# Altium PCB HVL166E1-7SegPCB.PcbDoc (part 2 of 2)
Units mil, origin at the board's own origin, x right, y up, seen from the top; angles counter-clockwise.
Board outline 2300 x 2421 mil, 2 copper layers (Top Layer, Bottom Layer), stack 62 mil thick; 193 components, 200 nets, 656 pads, 241 vias.
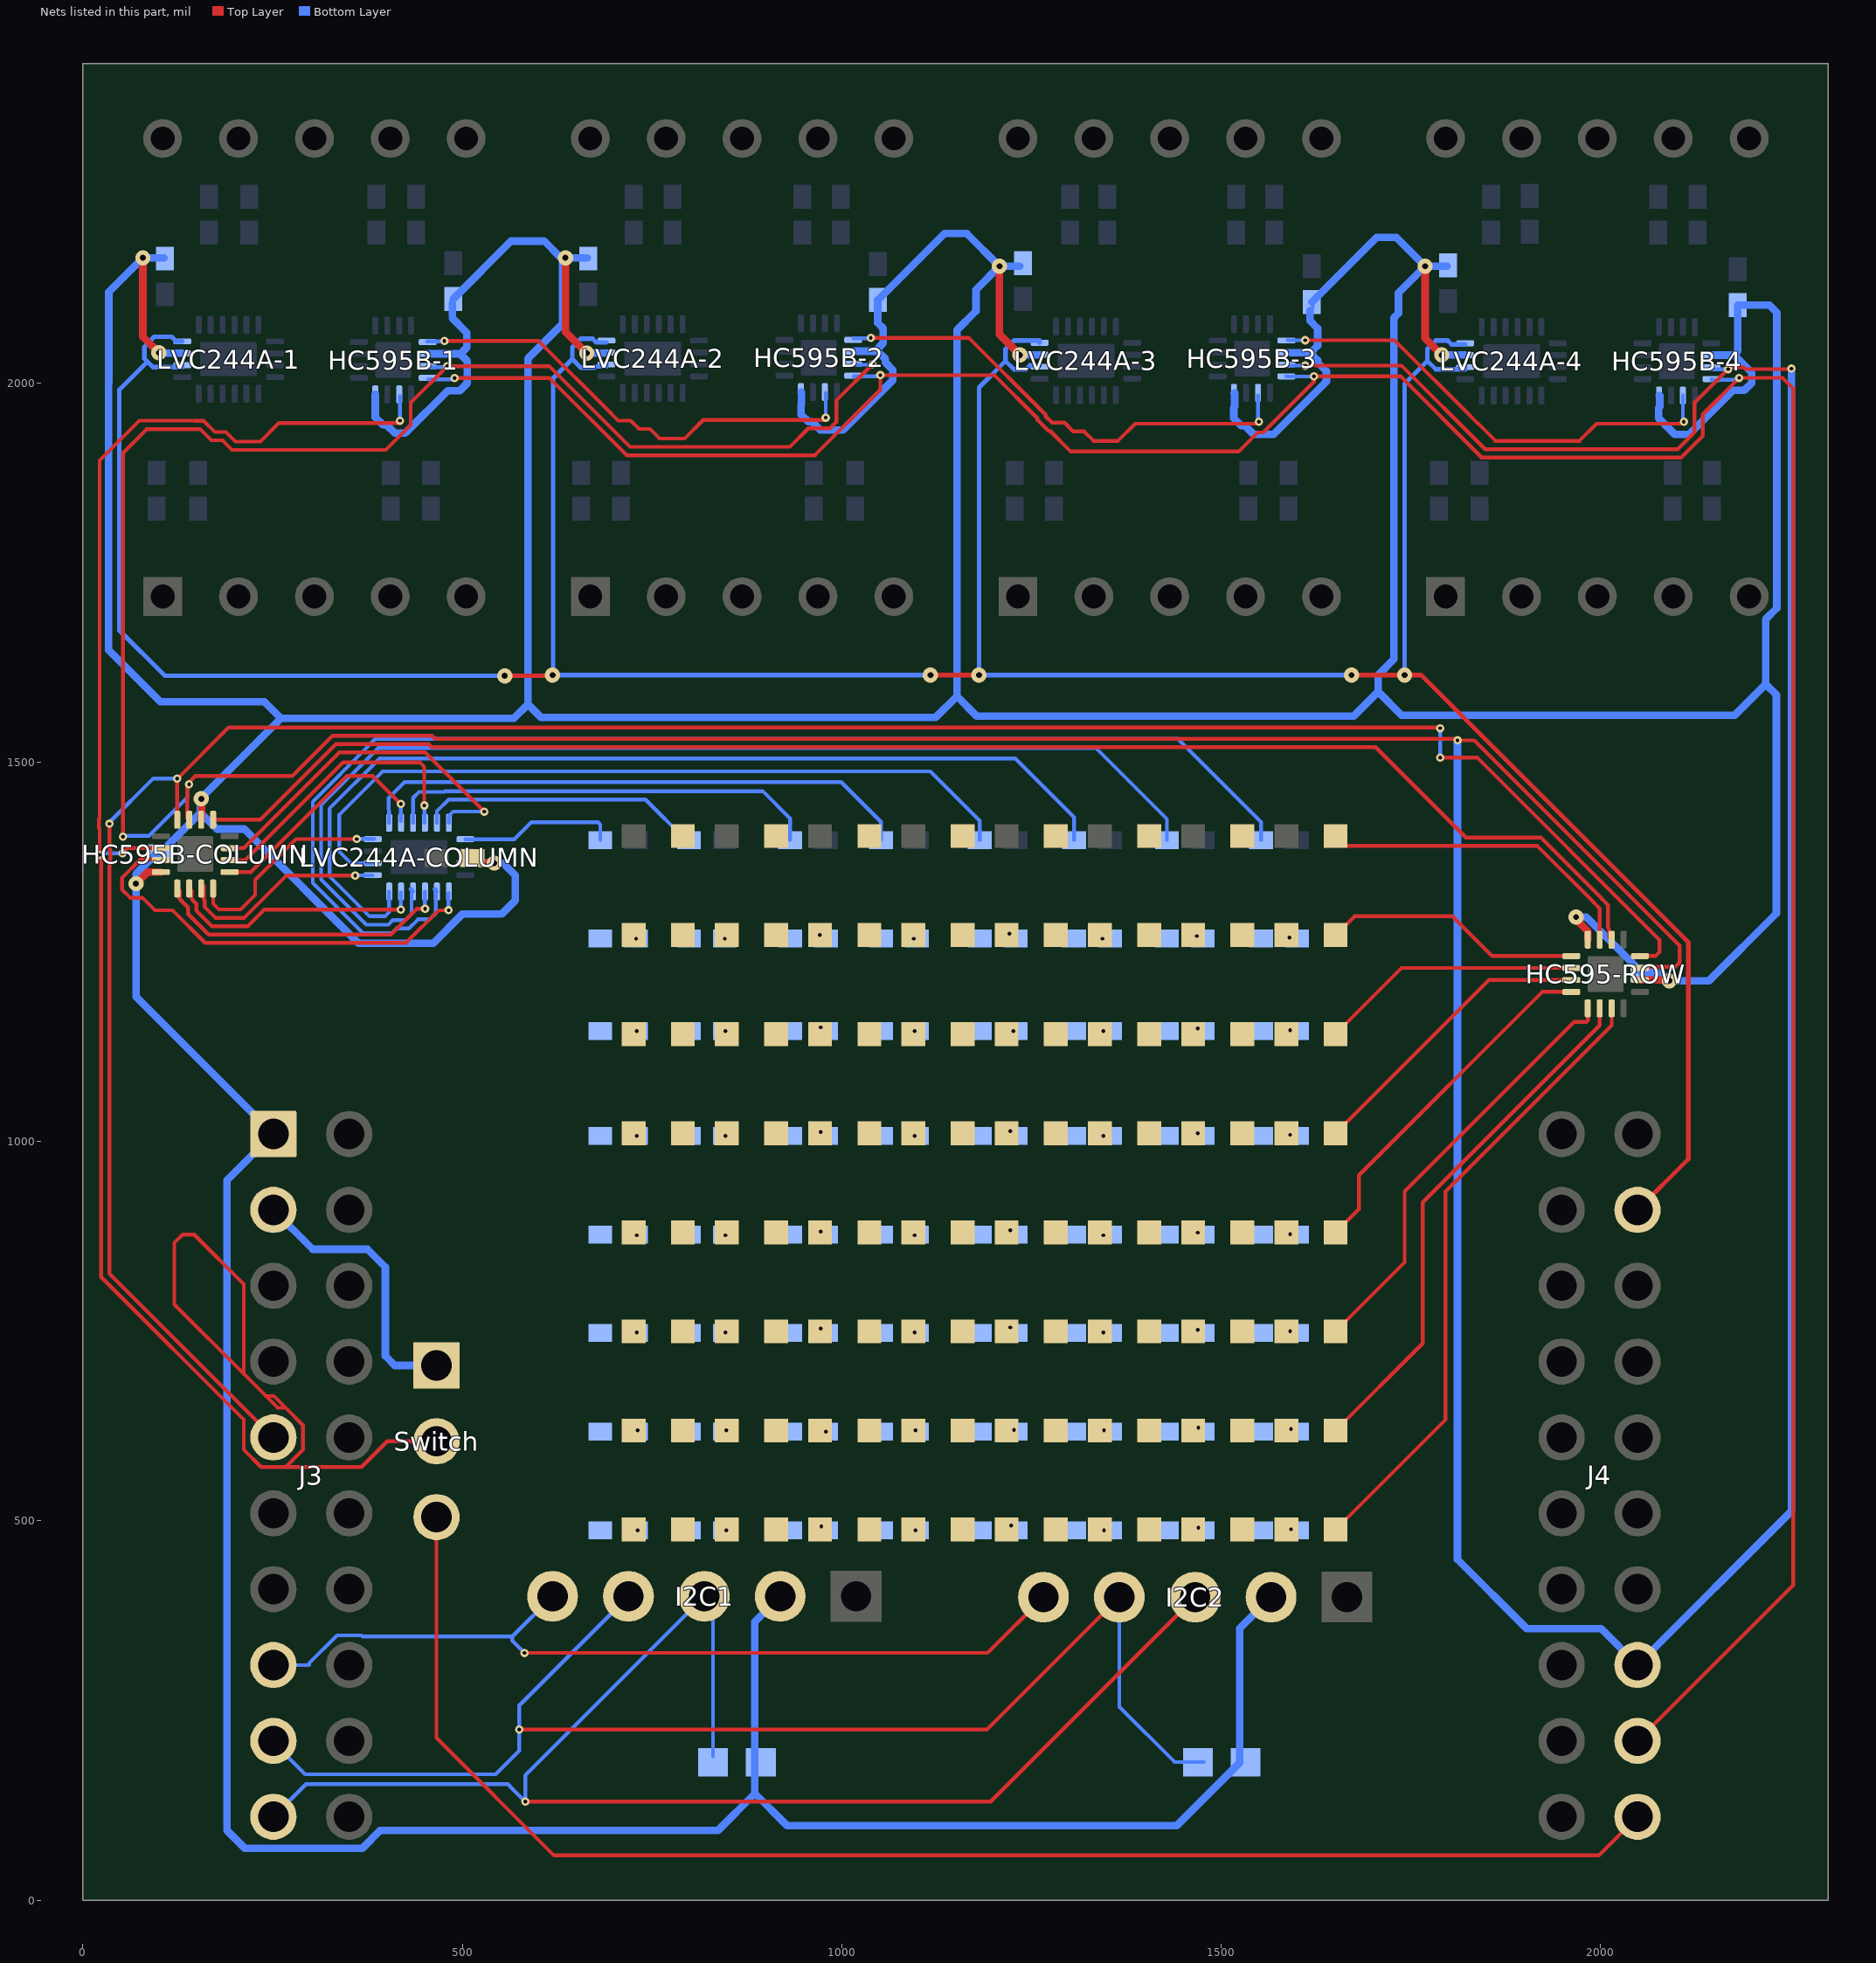
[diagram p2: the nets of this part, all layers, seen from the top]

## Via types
v1: diameter 11, hole 5, Top Layer to Bottom Layer, 172 vias
v2: diameter 20, hole 8, Top Layer to Bottom Layer, 36 vias
v3: diameter 19.68, hole 7.87, Top Layer to Bottom Layer, 27 vias
v4: diameter 24, hole 10, Top Layer to Bottom Layer, 6 vias

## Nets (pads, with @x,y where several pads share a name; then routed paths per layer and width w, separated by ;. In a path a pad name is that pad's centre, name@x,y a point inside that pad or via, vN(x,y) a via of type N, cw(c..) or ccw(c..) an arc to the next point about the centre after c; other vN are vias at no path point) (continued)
NetD2A_1: D2A.1 R2A.1
  other v1: 729.11,1267.57
NetD2B_1: D2B.1 R2B.1
  other v1: 846.03,1267.57
NetD2C_1: D2C.1 R2C.1
  other v1: 971.31,1272.58
NetD2D_1: D2D.1 R2D.1
  other v1: 1095.24,1267.57
NetD2E_1: D2E.1 R2E.1
  other v1: 1221.32,1274
NetD2F_1: D2F.1 R2F.1
  other v1: 1343.77,1267.57
NetD2G_1: D2G.1 R2G.1
  other v1: 1468.18,1271
NetD2H_1: D2H.1 R2H.1
  other v1: 1590.19,1269
NetD3A_1: D3A.1 R3A.1
  other v1: 730.11,1145.57
NetD3B_1: D3B.1 R3B.1
  other v1: 847.03,1145.57
NetD3C_1: D3C.1 R3C.1
  other v1: 972.31,1150.58
NetD3D_1: D3D.1 R3D.1
  other v1: 1096.24,1145.57
NetD3E_1: D3E.1 R3E.1
  other v1: 1226.26,1145.57
NetD3F_1: D3F.1 R22.1
  other v1: 1344.77,1145.57
NetD3G_1: D3G.1 R23.1
  other v1: 1469.18,1149
NetD3H_1: D3H.1 R24.1
  other v1: 1591.19,1147
NetD4A_1: D4A.1 R4A.1
  other v1: 730.11,1007.57
NetD4B_1: D4B.1 R4B.1
  other v1: 847.03,1007.57
NetD4C_1: D4C.1 R4C.1
  other v1: 972.31,1012.58
NetD4D_1: D4D.1 R4D.1
  other v1: 1096.24,1007.57
NetD4E_1: D4E.1 R4E.1
  other v1: 1222.32,1014
NetD4F_1: D4F.1 R30.1
  other v1: 1344.77,1007.57
NetD4G_1: D4G.1 R31.1
  other v1: 1469.18,1011
NetD4H_1: D4H.1 R32.1
  other v1: 1591.19,1009
NetD5A_1: D5A.1 R5A.1
  other v1: 730.11,876.57
NetD5B_1: D5B.1 R5B.1
  other v1: 847.03,876.57
NetD5C_1: D5C.1 R5C.1
  other v1: 972.31,881.58
NetD5D_1: D5D.1 R5D.1
  other v1: 1096.24,876.57
NetD5E_1: D5E.1 R5E.1
  other v1: 1222.32,883
NetD5F_1: D5F.1 R38.1
  other v1: 1344.77,876.57
NetD5G_1: D5G.1 R39.1
  other v1: 1469.18,880
NetD5H_1: D5H.1 R40.1
  other v1: 1591.19,878
NetD6A_1: D6A.1 R6A.1
  other v1: 730.11,748.57
NetD6B_1: D6B.1 R6B.1
  other v1: 847.03,748.57
NetD6C_1: D6C.1 R6C.1
  other v1: 972.31,753.58
NetD6D_1: D6D.1 R6D.1
  other v1: 1096.24,748.57
NetD6E_1: D6E.1 R6E.1
  other v1: 1222.32,755
NetD6F_1: D6F.1 R46.1
  other v1: 1344.77,748.57
NetD6G_1: D6G.1 R47.1
  other v1: 1469.18,752
NetD6H_1: D6H.1 R48.1
  other v1: 1591.19,750
NetD7A_1: D7A.1 R7A.1
  other v1: 731.11,619.57
NetD7B_1: D7B.1 R7B.1
  other v1: 848.03,619.57
NetD7C_1: D7C.1 R7C.1
  other v1: 979.14,617.57
NetD7D_1: D7D.1 R7D.1
  other v1: 1097.24,619.57
NetD7E_1: D7E.1 R7E.1
  other v1: 1227.21,620
NetD7F_1: D7F.1 R54.1
  other v1: 1345.77,619.57
NetD7G_1: D7G.1 R55.1
  other v1: 1470.18,623
NetD7H_1: D7H.1 R56.1
  other v1: 1592.19,621
NetD8A_1: D8A.1 R8A.1
  other v1: 731.11,487.57
NetD8B_1: D8B.1 R8B.1
  other v1: 848.03,487.57
NetD8C_1: D8C.1 R8C.1
  other v1: 973.31,492.58
NetD8D_1: D8D.1 R8D.1
  other v1: 1097.24,487.57
NetD8E_1: D8E.1 R8E.1
  other v1: 1223.32,494
NetD8F_1: D8F.1 R62.1
  other v1: 1345.77,487.57
NetD8G_1: D8G.1 R63.1
  other v1: 1470.18,491
NetD8H_1: D8H.1 R64.1
  other v1: 1592.19,489
NetHC595B-COLUMN_1: HC595B-COLUMN.1 LVC244A-COLUMN.3 | length 399.9
  Top Layer w5: HC595B-COLUMN.1@124.38,1333.72 127.69,1330.41 127.69,1319.55 138.62,1308.61 138.62,1299.95 165.58,1273 406.06,1273 440.06,1307 v1(451,1307)
  Bottom Layer w5: v1@450.87,1307.13 LVC244A-COLUMN.3@450.87,1329.72
NetHC595B-COLUMN_2: HC595B-COLUMN.2 LVC244A-COLUMN.5 | length 342.8
  Top Layer w5: HC595B-COLUMN.2@140.13,1333.72 143.44,1330.41 143.44,1319.55 149.62,1313.36 149.62,1304.51 170.13,1284 217.11,1284 238.98,1305.87 v1(419.13,1305.87)
  Bottom Layer w5: v1@419,1306 LVC244A-COLUMN.5@419,1328.59
NetHC595B-COLUMN_3: HC595B-COLUMN.3 LVC244A-COLUMN.7 | length 278.4
  Top Layer w5: HC595B-COLUMN.3@159.18,1337.03 159.18,1319.55 160.62,1318.11 160.62,1309.07 174.69,1295 212.56,1295 268.43,1350.87 v1(358.87,1350.87)
  Bottom Layer w5: v1@359,1351 LVC244A-COLUMN.7@381.59,1351
NetHC595B-COLUMN_4: HC595B-COLUMN.4 LVC244A-COLUMN.10 | length 285.4
  Top Layer w5: HC595B-COLUMN.4@171.62,1333.72 171.62,1313.62 179.24,1306 208,1306 227,1325 227,1345 280.87,1398.87 v1(361,1398.87)
  Bottom Layer w5: v1@361.13,1399 LVC244A-COLUMN.10@383.72,1399
NetHC595B-COLUMN_5: HC595B-COLUMN.5 LVC244A-COLUMN.12 | length 315.9
  Top Layer w5: HC595B-COLUMN.5@193.28,1355.38 221.38,1355.38 348,1482 382,1482 v1(418.87,1445.13)
  Bottom Layer w5: LVC244A-COLUMN.12@419,1422.41 v1@419,1445
NetHC595B-COLUMN_6: HC595B-COLUMN.6 LVC244A-COLUMN.14 | length 386
  Top Layer w5: HC595B-COLUMN.6@193.28,1371.13 214.13,1371.13 343,1500 444,1500 449.87,1494.13 v1(449.87,1443.13)
  Bottom Layer w5: LVC244A-COLUMN.14@450,1420.41 v1@450,1443
NetHC595B-COLUMN_7: HC595B-COLUMN.7 LVC244A-COLUMN.16 | length 478.3
  Top Layer w5: HC595B-COLUMN.7@193.28,1386.87 211.87,1386.87 338,1513 451,1513 v1(529,1435)
  Bottom Layer w5: LVC244A-COLUMN.16@482.37,1420.27 482.37,1429.37 488,1435 v1(529,1435)
NetHC595B-COLUMN_15: HC595B-COLUMN.15 LVC244A-COLUMN.1 | length 576.1
  Top Layer w5: HC595B-COLUMN.15@101.9,1371.95 75.79,1371.95 51.92,1348.08 51.5,1348.08 51.5,1332.34 62.34,1321.5 78.5,1321.5 95,1305 118.02,1305 161.02,1262 425.8,1262 468.8,1305 v1(482,1305)
  Bottom Layer w5: v1@481.87,1305.13 LVC244A-COLUMN.1@481.87,1327.72
NetJ4_11: J4.11 Switch.3 | length 1959.3
  Top Layer w5: Switch.3@466,505 466,214 621,59 1998,59 J4.11@2049,110
NetLVC244A-COLUMN_2: LVC244A-COLUMN.2 R1H.2 R2H.2 R24.2 R32.2 R40.2 R48.2 R56.2 R64.2 | length 1699.1
  Bottom Layer w5: LVC244A-COLUMN.2@466.62,1329.72 LVC244A-COLUMN.2@465,1331.34 ; R1H.2@1552.79,1397.57 1552.79,1421.21 1443,1531 385.89,1531 384.89,1530 384.44,1530 378,1523.56 378,1523.11 303,1448.11 303,1340.89 368.89,1275 407.11,1275 412.98,1280.87 429.48,1280.87 441.61,1293 456.8,1293 465,1301.2 LVC244A-COLUMN.2@465,1331.34 ; LVC244A-COLUMN.2@465,1331.34 465,1333.03 463.31,1333.03 LVC244A-COLUMN.2@465,1331.34
NetLVC244A-COLUMN_4: LVC244A-COLUMN.4 R1G.2 R2G.2 R23.2 R31.2 R39.2 R47.2 R55.2 R63.2 | length 1499.4
  Bottom Layer w5: LVC244A-COLUMN.4@435.12,1329.72 LVC244A-COLUMN.4@433.13,1331.71 ; R1G.2@1428.79,1397.57 1428.79,1425.21 1335,1519 389,1519 389,1518.56 314,1443.56 314,1345.44 373.44,1286 402.56,1286 408.43,1291.87 424.93,1291.87 433.13,1300.07 LVC244A-COLUMN.4@433.13,1331.71 ; LVC244A-COLUMN.4@433.13,1331.71 433.13,1333.03 431.81,1333.03 LVC244A-COLUMN.4@433.13,1331.71
NetLVC244A-COLUMN_6: LVC244A-COLUMN.6 R1F.2 R2F.2 R22.2 R30.2 R38.2 R46.2 R54.2 R62.2 | length 1289.8
  Bottom Layer w5: LVC244A-COLUMN.6@403.63,1329.72 403.63,1302.63 398,1297 378,1297 325,1350 325,1439 391,1505 1229,1505 1306.35,1427.65 R1F.2@1306.35,1397.57
NetLVC244A-COLUMN_8: LVC244A-COLUMN.8 R1E.2 R2E.2 R3E.2 R4E.2 R5E.2 R6E.2 R7E.2 R8E.2 | length 1018.9
  Bottom Layer w5: LVC244A-COLUMN.8@381.97,1367.12 353.12,1367.12 338,1382.24 338,1431 395,1488 1117,1488 1181.93,1423.07 R1E.2@1181.93,1397.57
NetLVC244A-COLUMN_11: LVC244A-COLUMN.11 R1D.2 R2D.2 R3D.2 R4D.2 R5D.2 R6D.2 R7D.2 R8D.2 | length 736
  Bottom Layer w5: LVC244A-COLUMN.11@403.63,1420.27 403,1453 424,1474 999.38,1474 1051.92,1421.47 R1D.2@1051.92,1397.57
NetLVC244A-COLUMN_13: LVC244A-COLUMN.13 R1C.2 R2C.2 R3C.2 R4C.2 R5C.2 R6C.2 R7C.2 R8C.2 | length 576.7
  Bottom Layer w5: LVC244A-COLUMN.13@435.12,1420.27 435.12,1453.12 443,1461 476.44,1461 477.44,1462 896,1462 931.9,1426.1 R1C.2@931.9,1397.57
NetLVC244A-COLUMN_15: LVC244A-COLUMN.15 R1B.2 R2B.2 R3B.2 R4B.2 R5B.2 R6B.2 R7B.2 R8B.2 | length 372.1
  Bottom Layer w5: LVC244A-COLUMN.15@466.62,1420.27 466.62,1435.62 482,1451 741.41,1451 R1B.2@794.84,1397.57
NetLVC244A-COLUMN_17: LVC244A-COLUMN.17 R1A.2 R2A.2 R3A.2 R4A.2 R5A.2 R6A.2 R7A.2 R8A.2 | length 208.9
  Bottom Layer w5: LVC244A-COLUMN.17@504.02,1398.62 568.62,1398.62 591,1421 679,1421 681.86,1418.14 R1A.2@681.86,1397.57
PIN2: J3.2 Switch.1 | length 402.5
  Bottom Layer w5: J3.2@251,910 J3.2@261,910 ; Switch.1@466,705 Switch.1@466,729
  Bottom Layer w10: J3.2@251,910 303,858 375,858 398.5,834.5 398.5,717.5 411,705 Switch.1@466,705
PWM: J4.19 LVC244A-1.18 LVC244A-1.20 LVC244A-2.18 LVC244A-2.20 LVC244A-3.18 LVC244A-3.20 LVC244A-4.18 LVC244A-4.20 | length 4779.9
  Top Layer w6: v2(556,1614) v2@618,1614 ; v2(1117,1615) v2(1181,1615) ; v2(1672,1615) v2(1742,1615) 1764,1615 2116,1263 2116,977 J4.19@2049,910
  Bottom Layer w2: LVC244A-1.20@122.99,2055.01 LVC244A-1.20@130.98,2055.01
  Bottom Layer w5: J4.19@2049,910 J4.19@2050,910
  Bottom Layer w6: 85,2028 48,1991 48,1674 108,1614 v2(556,1614) ; LVC244A-1.20@122,2055 LVC244A-1.20@130.98,2055.01 ; LVC244A-1.20@122.99,2055.01 117,2061 94.13,2061 81,2047.87 81,2032.13 92.13,2021 130.98,2021 LVC244A-1.18@130.98,2023.52 ; v2(619,1615) v2(1117,1615) ; v2@619.87,1615.87 619.87,2006.39 645,2031.52 ; LVC244A-2.18@689.98,2024.52 689.98,2021.71 675.59,2021.71 674.28,2020.39 656.13,2020.39 645,2031.52 ; LVC244A-2.20@689.98,2053.45 676.81,2053.45 671.87,2058.39 656.13,2058.39 645,2047.26 645,2031.52 ; LVC244A-3.18@1260.98,2023.26 1248.13,2023.26 1242.87,2018 1227.13,2018 1216,2029.13 ; LVC244A-3.20@1260.98,2053.01 1260.98,2056 1227.13,2056 1216,2044.87 1216,2029.13 ; v2(1672,1615) v2(1181,1615) 1181,1994.13 1216,2029.13 ; v2(1742,1615) 1742,1999.13 1772,2029.13 ; LVC244A-4.18@1821.98,2020.96 1821.98,2018.15 1807.59,2018.15 1807.44,2018 1783.13,2018 1772,2029.13 ; LVC244A-4.20@1821.98,2051 1803.87,2051 1798.87,2056 1783.13,2056 1772,2044.87 1772,2029.13
QA: D1A.2 D1B.2 D1C.2 D1D.2 D1E.2 D1F.2 D1G.2 D1H.2 HC595-ROW.15 | length 428.8
  Top Layer w5: D1H.2@1651.09,1402.83 1664.18,1389.74 1917.03,1389.74 1991.16,1315.6 1991.16,1315.21 1999.13,1307.25 HC595-ROW.15@1999.13,1266.28
QB: D2A.2 D2B.2 D2C.2 D2D.2 D2E.2 D2F.2 D2G.2 D2H.2 HC595-ROW.1 | length 342.6
  Top Layer w5: D2H.2@1651.09,1272.22 1651.22,1272.22 1676,1297 1805,1297 1857.38,1244.62 HC595-ROW.1@1961.72,1244.62
QC: D3A.2 D3B.2 D3C.2 D3D.2 D3E.2 D3F.2 D3G.2 D3H.2 HC595-ROW.2 | length 349.2
  Top Layer w5: D3H.2@1651.09,1142.09 1737.87,1228.87 1793.87,1228.87 HC595-ROW.2@1961.72,1228.87 HC595-ROW.2@1960.19,1230.41
  Top Layer w6: D3H.2@1651.09,1141.61 D3H.2@1651.09,1142.09
QD: D4A.2 D4B.2 D4C.2 D4D.2 D4E.2 D4F.2 D4G.2 D4H.2 HC595-ROW.3 | length 395.7
  Top Layer w5: D4H.2@1651.09,1011 1651.09,1011.09 1853.13,1213.13 HC595-ROW.3@1961.72,1213.13 HC595-ROW.3@1960.79,1212.19
QE: D5A.2 D5B.2 D5C.2 D5D.2 D5E.2 D5F.2 D5G.2 D5H.2 HC595-ROW.4 | length 468.1
  Top Layer w5: D5H.2@1651.09,880.39 1681.7,911 1681.7,955.7 1923.38,1197.38 HC595-ROW.4@1961.72,1197.38
QF: D6A.2 D6B.2 D6C.2 D6D.2 D6E.2 D6F.2 D6G.2 D6H.2 HC595-ROW.5 | length 573.2
  Top Layer w5: D6H.2@1651.09,749.78 1742,840.7 1742,934.35 1797.91,990.26 1909.74,1102.09 1965.65,1158 1982,1158 1983.38,1159.38 HC595-ROW.5@1983.38,1175.72
QG: D7A.2 D7B.2 D7C.2 D7D.2 D7E.2 D7F.2 D7G.2 D7H.2 HC595-ROW.6 | length 701.9
  Top Layer w5: D7H.2@1651.09,619.17 1766,734.09 1766,920 1999.13,1153.13 HC595-ROW.6@1999.13,1175.72 HC595-ROW.6@2000,1174.85
QH: D8A.2 D8B.2 D8C.2 D8D.2 D8E.2 D8F.2 D8G.2 D8H.2 HC595-ROW.7 | length 837.8
  Top Layer w5: D8H.2@1651.09,488.57 1796,633.48 1796,934.44 2014.87,1153.32 HC595-ROW.7@2014.87,1175.72
QH1: HC595-ROW.14 HC595B-COLUMN.9 | length 2015.4
  Top Layer w5: HC595B-COLUMN.9@171.62,1424.28 233.72,1424.28 333.44,1524 455.56,1524 459.56,1520 1703.74,1520 1823,1400.74 1921.59,1400.74 2002.16,1320.16 2002.16,1319.76 2010.13,1311.8 2010.13,1281.89 2011.56,1280.45 2011.56,1269.59 HC595-ROW.14@2014.87,1266.28
QH'1: HC595B-1.9 HC595B-2.14 | length 622.3
  Top Layer w5: v1(476.38,2055.38) 600.82,2055.38 697.38,1958.82 697.38,1958.64 705.58,1950.44 722.02,1950.44 733.02,1939.44 747.47,1939.44 760.09,1926.82 792.91,1926.82 817.49,1951.39 976,1951.39 v1(979,1954.39)
  Bottom Layer w5: HC595B-1.9@453.65,2055 v1@476,2055 ; v1(979,1954.39) HC595B-2.14@979,1986.99
QH'2: HC595B-2.9 HC595B-3.14 | length 638.5
  Top Layer w5: v1(1038.38,2059.38) 1167.82,2059.38 1269,1958.2 1269,1956.02 1277.2,1947.82 1293.64,1947.82 1305.02,1936.44 1319.47,1936.44 1332.09,1923.82 1364.29,1923.82 1386.93,1946.45 1547.62,1946.45 v1(1550,1948.83) ; v1@1549.75,1946.58 v1@1552,1948.83
  Bottom Layer w5: HC595B-2.9@1015.65,2059 v1@1038,2059 ; v1@1548.87,1949.96 HC595B-3.14@1548.87,1983.56
QH'3: HC595B-3.9 HC595B-4.14 | length 620.9
  Top Layer w5: v1(1611,2056.39) 1728.81,2056.39 1829.38,1955.82 1829.38,1955.64 1837.58,1947.44 1838.01,1947.44 1861.63,1923.82 1972.47,1923.82 1995.11,1946.45 2107.62,1946.45 v1(2110,1948.83)
  Bottom Layer w5: HC595B-3.9@1588.11,2056.52 v1(1611,2056.39) ; v1@2108.87,1949.96 HC595B-4.14@2108.87,1983.56
RCLK: HC595B-1.12 HC595B-2.12 HC595B-3.12 HC595B-4.12 J4.12 | length 4064.7
  Top Layer w5: v1(490,2006.39) 615.05,2006.39 716.63,1904.82 964.78,1904.82 1051,1991.04 v1(1051,2010.39) 1201.25,2010.39 1258,1953.64 1258,1951.46 1272.64,1936.82 1274.82,1936.82 1301.64,1910 1523.61,1910 1548.44,1934.83 1555.8,1934.83 1622.38,2001.41 v1(1622.38,2008.77) 1736.68,2008.77 1843.63,1901.82 2106.37,1901.82 ; J4.12@2049,210 2254,415 2254,1993 2240.17,2006.83 v1(2183,2006.83) 2135,1958.83 2135,1930.44 2106.37,1901.82 ; 2106.37,1901.63 2106.37,1901.82
  Bottom Layer w5: HC595B-1.12@455.28,2004.77 v1@488.38,2004.77 ; HC595B-2.12@1016.28,2008.77 v1@1049.38,2008.77 ; HC595B-3.12@1586.11,2008.77 v1@1622,2008.39 ; HC595B-4.12@2146.28,2005.21 2146.28,2004.38 v1@2180.55,2004.38
RCLKM: HC595-ROW.12 HC595B-COLUMN.12 J3.5 | length 3233.6
  Top Layer w5: v1(35,1419) 35,1384.8 36,1384.8 36,1372.2 35,1371.2 35,826 J3.5@251,610 ; HC595B-COLUMN.12@124.38,1424.28 v1(124.38,1478.38) 192,1546 1788,1546 v1(1789,1545) ; v1(1789,1506) 1838,1506 2078.09,1265.91 2078.09,1250.09 2072.62,1244.62 HC595-ROW.12@2052.28,1244.62
  Bottom Layer w5: v1(35,1419) 35,1421 92.38,1478.38 v1(124.38,1478.38) ; v1(1789,1506) v1(1789,1545)
SCL: I2C1.4 I2C2.4 J3.9 PU-SCL.1 | length 1786.7
  Top Layer w5: v1(575,225) 1191.46,225 I2C2.4@1366,399.54
  Bottom Layer w5: J3.9@266,210 249,210 293,166 544,166 575,197 v1(575,225) 575,256.54 I2C1.4@719,400.54 ; I2C2.4@1366,399.54 1366,255 1439,182 PU-SCL.1@1477.38,182
SDA: I2C1.3 I2C2.3 J3.10 PU-SDA.1 | length 1938
  Top Layer w5: v1(583,130) 1196.46,130 I2C2.3@1466,399.54
  Bottom Layer w5: J3.10@251,110 294,153 560,153 565.98,147.02 ; 565.98,147.51 565.98,147.02 ; PU-SDA.1@830.38,190 830.38,389.16 I2C1.3@819,400.54 583,164.54 v1(583,130) 565.98,147.02
SER: HC595B-1.14 HC595B-COLUMN.14 Switch.2 | length 2876.8
  Top Layer w5: v1(52,1380) 58.87,1386.87 HC595B-COLUMN.14@102.72,1386.87 ; v1(418,1950.39) 415.06,1947.45 258.49,1947.45 233.85,1922.82 201.09,1922.82 188.47,1935.44 174.02,1935.44 159.45,1950.01 147.58,1950.01 147.2,1950.39 74.39,1950.39 22,1898 22,1425.8 21,1425.8 21,1413.2 22,1412.2 v1(22,1378) 24.12,1375.88 24,1375.88 24,821.44 211.99,633.46 211.99,593.84 234.84,570.99 267.16,570.99 ; Switch.2@466,605 401.17,605 367.16,570.99 267.16,570.99 ; 211.99,693.84 241.26,664.57 ; 211.99,693.84 211.99,812.17 146.66,877.5 131.34,877.5 120.5,866.66 120.5,785.33 211.99,693.84 ; 241.26,664.57 251.6,664.57 267.16,649.01 ; 241.26,664.57 256.82,649.01 267.16,649.01 ; 267.16,570.99 290.01,593.84 290.01,626.16 267.16,649.01
  Bottom Layer w5: v1@19,1380 v1(52,1380) ; v1(418,1950.39) HC595B-1.14@418,1982.99
SRCLK: HC595-ROW.11 HC595B-1.11 HC595B-2.11 HC595B-3.11 HC595B-4.11 HC595B-COLUMN.11 J4.13 | length 8060.8
  Top Layer w5: v1(53,1402) 53,1908 84.01,1939.01 154.89,1939.01 169.47,1924.44 183.91,1924.44 196.53,1911.82 399.22,1911.82 432,1944.59 432,1974 v1(480,2022) 615,2022 721.18,1915.82 931.82,1915.82 956.39,1940.39 984.8,1940.39 993,1948.59 993,1977 v1(1041,2025) ; v1@137.5,1468.5 137.5,1426.9 HC595B-COLUMN.11@140.13,1424.28 ; v1(140,1471) 140,1474 148.06,1482.06 275.94,1482.06 328.89,1535 460.11,1535 464.11,1531 1809.71,1531 v1(1811.71,1529) 1833.74,1529 2104.5,1258.24 2104.5,1236 2099,1230.5 HC595-ROW.11@2053.9,1230.5 ; v1(1611,2023) 1738,2023 1848.18,1912.82 2101.82,1912.82 2124,1935 2124,1974 v1(2168.38,2018.38) 2170.83,2020.83 2188.8,2020.83 2191.25,2018.38 2251.38,2018.38 v1(2252,2019)
  Bottom Layer w5: v1@57,1403 87,1403 137.5,1453.5 137.5,1468.5 v1(140,1471) ; HC595B-1.11@454.28,2021.13 v1@479.13,2021.13 ; HC595B-2.11@1015.28,2024.13 v1@1040.13,2024.13 ; HC595B-3.11@1588.11,2023.13 v1(1611,2023) ; HC595B-4.11@2137.65,2018 v1@2168,2018
  Bottom Layer w10: v1(1811.71,1529) 1811.71,449.29 1903,358 2001,358 J4.13@2049,310 2252,513 v1(2252,2019)
VCC: C1.1 C2.1 C3.1 C4.1 C5.1 C6.1 C7.1 C8.1 C9.1 C10.1 C11.1 HC595-ROW.10 HC595-ROW.16 HC595B-1.10 HC595B-1.16 HC595B-2.10 HC595B-2.16 HC595B-3.10 HC595B-3.16 HC595B-4.10 HC595B-4.16 HC595B-COLUMN.10 HC595B-COLUMN.16 I2C1.2 I2C2.2 J3.1 LVC244A-1.19 LVC244A-2.19 LVC244A-3.19 LVC244A-4.19 LVC244A-COLUMN.19 PU-SCL.2 PU-SDA.2 | length 12897
  Top Layer w10: v2(70,1340) 85.38,1355.38 HC595B-COLUMN.16@102.72,1355.38 ; v2(79,2165) 79,2061 v2(100,2040) ; HC595B-COLUMN.10@155.87,1424.28 v2@156.87,1451.13 ; C10.1@520.5,1367.12 v2(542.12,1367.12) ; v2(636,2165) 636,2067.39 v2(664,2039.39) ; v2(1208,2154) 1208,2064 v2(1235,2037) ; v2(1769,2154) 1769,2059 v2(1791,2037) ; v2@1968,1293 1983.38,1277.62 HC595-ROW.16@1983.38,1266.28 ; HC595-ROW.10@2052.28,1213.13 v2@2089.87,1213.13
  Bottom Layer w5: C11.1@97,1380 C11.1@101.38,1380 ; C6.1@1621,2099.39 C6.1@1621,2102.77
  Bottom Layer w6: C9.1@2051.62,1226 C9.1@2056.62,1226
  Bottom Layer w10: C11.1@97,1380 70,1353 v2(70,1340) 70,1191 J3.1@251,1010 190,949 190,92 213.51,68.49 368.19,68.49 391.71,92 837,92 885.62,140.62 ; v2@100.74,2039.26 LVC244A-1.19@130.98,2039.26 ; C11.1@101.38,1380 155,1433.62 ; C1.1@107.01,2165 v2(79,2165) 34,2120 34,2000.93 33.87,2000.8 33.87,1648.19 102.06,1580 239,1580 261,1558 ; 385.38,1955.12 395.54,1944.95 400.1,1944.95 411.17,1933.89 424.83,1933.89 480.83,1989.89 496.83,1989.89 506.5,1999.56 506.5,2029.03 497.26,2038.26 ; 385.38,1955.38 HC595B-1.16@385.38,1985.11 ; HC595B-1.10@454.51,2038.5 497.03,2038.5 497.26,2038.26 ; C2.1@486.83,2105.77 486.83,2085.36 506,2066.19 506,2047 497.26,2038.26 ; C2.1@488,2110.77 564.23,2187 608.08,2187 630.08,2165 v2(636,2165) ; LVC244A-COLUMN.19@504.02,1367.12 v2(542.12,1367.12) 553.88,1367.12 570,1351 570,1318 552,1300 500.33,1300 461.83,1261.5 363.3,1261.5 212.8,1412 176.62,1412 155,1433.62 ; v2(664,2039.39) 664.06,2039.45 LVC244A-2.19@689.16,2039.45 ; C3.1@665.01,2165 v2(636,2165) ; I2C1.2@919,400.54 885.62,367.16 885.62,140.62 ; HC595B-2.16@946.38,1988.11 947.19,1988.11 947.19,1972.21 947,1972.02 ; 946.5,1972.02 946.5,1958.56 956.17,1948.89 961.17,1948.89 972.17,1937.89 1001.83,1937.89 1067.5,2003.56 1067.5,2017.22 1057.5,2027.22 1057.5,2031.83 1047.26,2042.08 1044.41,2042.08 ; HC595B-2.10@1016.09,2042.08 1044.41,2042.08 ; C4.1@1047.63,2109.4 1047.63,2079.51 1054.88,2072.26 1054.88,2052.54 1044.41,2042.08 ; C4.1@1048,2109.77 1135.23,2197 1165,2197 v2(1208,2154) ; C5.1@1234.99,2154 v2(1208,2154) ; v2@1235.26,2037.26 LVC244A-3.19@1260.98,2037.26 ; 1516.88,1967.34 1516.88,1953.62 1526.54,1943.95 1531.54,1943.95 1543.17,1932.33 1569.28,1932.33 1638.88,2001.93 1638.88,2015.6 1627.5,2026.98 1627.5,2029.83 1617.83,2039.5 1617.83,2039.89 ; 1517,1967.46 1518.02,1968.48 1518.02,1987.11 HC595B-3.16@1517.21,1987.11 ; I2C2.2@1566,399.54 1524.62,358.16 1524.62,181.11 1441.76,98.24 928,98.24 885.62,140.62 ; HC595B-3.10@1586.48,2039.89 1617.83,2039.89 ; C6.1@1617.17,2095.56 1617.17,2082.22 1627.5,2071.89 1627.5,2049.56 1617.83,2039.89 ; C6.1@1619.83,2106.77 1705.06,2192 1731,2192 v2(1769,2154) ; v2(1791,2037) LVC244A-4.19@1821.68,2037 ; C7.1@1797.99,2154 v2(1769,2154) ; v2(1968,1296) 1981.62,1296 2051.62,1226 C9.1@2055.62,1222 2081,1222 v2(2091,1212) 2143,1212 2232,1301 2232,1589 2218,1603 ; 2077,1967.41 2076.88,1967.29 2076.88,1953.62 2098.17,1932.33 2116.83,1932.33 2174.83,1990.33 2189.83,1990.33 2199.5,2000 2199.5,2013.67 2178.29,2034.88 2177.58,2034.88 ; 2077,1967.46 2078.19,1968.65 2078.19,1983.56 HC595B-4.16@2077.38,1983.56 ; HC595B-4.10@2146.28,2036.71 2175.71,2036.71 ; 2175.63,2036.83 2175.73,2036.73 2181,2042 C8.1@2181,2102.77 2222.77,2102.77 2232.65,2092.88 2232.65,1703.33 2218,1688.68 2218,1603 ; 155,1433.62 155,1452 261,1558 ; 261,1558 568,1558 586.5,1576.5 ; 586.5,1576.5 604,1559 1124,1559 1152,1587 ; 586.5,1576.5 586.5,2032.5 632,2078 632,2161 v2(636,2165) ; 1152,1587 1178,1561 1675,1561 1707,1593 ; 1152,1587 1152,2070 1177,2095 1177,2123 v2(1208,2154) ; 1707,1593 1738,1562 2177,1562 2218,1603 ; 1707,1593 1707,1615 1728,1636 1728,2086 1734,2092 1734,2119 v2(1769,2154)
  other v2: 156,1452
~INT: I2C1.5 I2C2.5 J3.8 | length 1150.6
  Top Layer w5: v1(582,326) 1192.46,326 I2C2.5@1266,399.54
  Bottom Layer w5: J3.8@251,310 297.95,310 297.95,312.12 334.84,349.01 367.16,349.01 368.66,347.51 565.98,347.51 ; v1(582,326) 565.98,342.02 565.98,347.51 ; I2C1.5@619,400.54 565.98,347.51
pads on no net: HC595-ROW.9 HC595B-4.9 J3.3 J3.4 J3.6 J3.7 J3.21 J3.22 J3.23 J3.24 J3.25 J3.26 J3.27 J3.28 J3.29 J3.30 J4.14 J4.15 J4.16 J4.17 J4.18 J4.31 J4.32 J4.33 J4.34 J4.35 J4.36 J4.37 J4.38 J4.39 J4.40 LVC244A-1. LVC244A-2. LVC244A-3. LVC244A-4. LVC244A-COLUMN.

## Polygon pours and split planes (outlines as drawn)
NetLVC244A-COLUMN_4 on Bottom Layer "BOTTOM_LAYER_NETLVC244A-COLUMN_4_P018" (solid, remove dead copper, pour order 18): 1445.72,1416.23 1400.72,1416.23 1399.72,1417.23 1400.72,1416.23 1400.72,464.23 1448.72,464.23 1449.72,465.23
NetLVC244A-COLUMN_8 on Bottom Layer "BOTTOM_LAYER_NETLVC244A-COLUMN_8_P014" (solid, remove dead copper, pour order 14): 1203.57,1417.23 1144.57,1417.23 1142.57,1415.23 1150.57,1407.23 1150.57,463.23 1201.57,463.23 1202.57,464.23
NetLVC244A-COLUMN_13 on Bottom Layer "BOTTOM_LAYER_NETLVC244A-COLUMN_13_P010" (solid, remove dead copper, pour order 10): 951.61,1415.23 895.61,1415.23 894.61,1414.23 904.61,1404.23 904.61,464.23 954.61,464.23
NetLVC244A-COLUMN_15 on Bottom Layer "BOTTOM_LAYER_NETLVC244A-COLUMN_15_P006" (solid, remove dead copper, pour order 6): 820,1416 775.41,1416 774.41,1417 773.2,1415.79 773.2,470 815,470 822,463
NetLVC244A-COLUMN_17 on Bottom Layer "BOTTOM_LAYER_NETLVC244A-COLUMN_17_P008" (solid, remove dead copper, pour order 8): 657.48,1413 704,1413 704,464 707,461 699,469 653,469
NetLVC244A-COLUMN_11 on Bottom Layer "BOTTOM_LAYER_NETLVC244A-COLUMN_11_P012" (solid, remove dead copper, pour order 12): 1076,1421 1071,1416 1023,1416 1023,477 1031,469 1035,465 1078,465
NetLVC244A-COLUMN_6 on Bottom Layer "BOTTOM_LAYER_NETLVC244A-COLUMN_6_P016" (solid, remove dead copper, pour order 16): 1331,1416 1275,1416 1275,465 1279,461 1332,461
NetLVC244A-COLUMN_2 on Bottom Layer "BOTTOM_LAYER_NETLVC244A-COLUMN_2_P020" (solid, remove dead copper, pour order 20): 1579,1419.22 1578.78,1419 1520,1419 1520,474 1532,462 1534,464 1576,464
GND on Bottom Layer "BOTTOM_LAYER_GND_P052" (solid, remove dead copper, pour order 52): 11,2400 2289,2400 2297,2408 2297,6 7,6
QA on Top Layer "TOP_LAYER_QA_P026" (solid, remove dead copper, pour order 26): 751,1474 1686,1474 1692,1468 1691,1467 1691,1363 754,1363 748,1357
QB on Top Layer "TOP_LAYER_QB_P032" (solid, remove dead copper, pour order 32): 770,1342 773,1339 1688,1339 1688,1240 1692,1236 1681,1225 766,1225
QC on Top Layer "TOP_LAYER_QC_P034" (solid, remove dead copper, pour order 34): 764,1211 1699,1211 1700,1212 1685,1197 1685,1100 769,1100 765,1096
QD on Top Layer "TOP_LAYER_QD_P038" (solid, remove dead copper, pour order 38): 767,1081 1686,1081 1690,1085 1688,1083 1688,981 763,981 762,980
QE on Top Layer "TOP_LAYER_QE_P040" (solid, remove dead copper, pour order 40): 763,955 763.7,955.7 1681.7,955.7 1681.7,854.7 1674,847 1664,837 763,837
QF on Top Layer "TOP_LAYER_QF_P042" (solid, remove dead copper, pour order 42): 768,821 1685,821 1686,820 1690,816 1690,715 766,715 763,712
QG on Top Layer "TOP_LAYER_QG_P044" (solid, remove dead copper, pour order 44): 765,690 1692,690 1692,585 1695,582 1694,581 759,581
QH on Top Layer "TOP_LAYER_QH_P046" (solid, remove dead copper, pour order 46): 765,566 1680,566 1682,564 1685,561 1685,459 767,459 763,455
GND on Top Layer "TOP_LAYER_GND_P050" (solid, remove dead copper, pour order 50): 2,2411 5,2408 2299,2408 2299,6 2296,3 2293,6 2,6

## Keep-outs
Keep-Out Layer:
  text ".Layer_Name" at 577,-858.49 h60

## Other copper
Top Layer:
  text ".Layer_Name" at 577,-858.49 h60
Bottom Layer:
  text ".Layer_Name" at 577,-858.49 h60

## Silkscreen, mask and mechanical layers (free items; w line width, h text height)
Top Overlay:
  drawing of 67 lines, arcs and shapes, not listed
  text "3" at 989,1440.63 h59.06
  text "5" at 1229,1440.63 h59.06
  text "6" at 1349,1440.63 h59.06
  text "8" at 1589,1440.63 h59.06
  text "1" at 749,1440 h59.06
  text "2" at 868.94,1440 h59.06
  text "4" at 1109,1440 h59.06
  text "7" at 1469,1440 h59.06
  text "A" at 627,1375 h72.83
  text "B" at 627,1244 h72.83
  text "C" at 624,1117 h72.83
  text "D" at 627,987 h72.83
  text "PWM" at 2148,895 h50
  text "*SER2" at 14,882 h45
  text "E" at 621,850 h72.83
  text "F" at 621,730 h72.83
  text "PIN2" at 529.03,695 h39.37
  text "SER" at 529.03,596 h39.37
  text "RCLKM" at 14,593 h45
  text "G" at 614,587 h72.83
  text "PIN11" at 529.03,493 h35.43
  text "H" at 614,473 h72.83
  text "INT" at 14,294 h45
  text "SRCLK" at 2146,292.75 h45
  text "SCL" at 14,191 h45
  text "RCLK" at 2143.5,187.88 h50
  text "BOOSTXL-SHIFTLED" at 1890.18,138.22 h50 r90
  text "Rev 1.0" at 1824,132 h70 r90
  text "For evaluation only; not FCC approved for resale." at 1765,127 h50 r90
  text "SDA" at 14,84 h45
  text "*SER1" at 2146,82 h50
  text "I2C1" at 533,42 h72.83 r90
  text "I2C2" at 1168,33.47 h72.83 r90
  text ".Layer_Name" at 577,-858.49 h60
Bottom Overlay:
  drawing of 3518 lines, arcs and shapes, not listed
  text "1" at 722,1434.78 h72.83
  text "3" at 970,1434.78 h72.83
  text "4" at 1093.25,1434.78 h72.83
  text "6" at 1343,1434.78 h72.83
  text "2" at 843,1434 h72.83
  text "5" at 1222.04,1434 h72.83
  text "7" at 1468,1434 h72.83
  text "8" at 1584,1434 h72.83
  text "A" at 1685.19,1379.58 h72.83
  text "B" at 1685.19,1248.16 h72.83
  text "C" at 1685.19,1117.51 h72.83
  text "J2" at 2168,1078 h72.83
  text "1" at 260,1076 h60
  text "21" at 380,1076 h60
  text "40" at 1978,1076 h60
  text "20" at 2077,1076 h60
  text "J1" at 197,1073.94 h72.83
  text "3V3" at 136,987.5 h72.83
  text "GND" at 2289,985.75 h72.83
  text "5V" at 557.25,985 h72.83
  text "D" at 1685.19,985.3 h72.83
  text "GND" at 592,885 h72.83
  text "E" at 1685.19,853.87 h72.83
  text "F" at 1685.19,722.44 h72.83
  text "G" at 1685.19,591.8 h72.83
  text "H" at 1685,466 h72.83
  text "INT" at 639,359 h72.83 r90
  text "SCL" at 741,359 h72.83 r90
  text "SDA" at 839,359 h72.83 r90
  text "3V3" at 938,359 h72.83 r90
  text "INT" at 1289,359 h72.83 r90
  text "SCL" at 1392,359 h72.83 r90
  text "SDA" at 1490,359 h72.83 r90
  text "3V3" at 1589,359 h72.83 r90
  text "GND" at 1691,358 h72.83 r90
  text "GND" at 1035,357 h72.83 r90
  text "7 SEGMENT AND LED MATRIX DISPLAY" at 1737,112 h72.83
  text "BOOSTXL-SHIFTLED" at 1738,49 h72.83
  text "Rev 1.0" at 1738,-2 h51.18
  text ".Layer_Name" at 577,-858.49 h60
Top Paste:
  text ".Layer_Name" at 577,-858.49 h60
Bottom Paste:
  text ".Layer_Name" at 577,-858.49 h60
Top Solder:
  text ".Layer_Name" at 577,-858.49 h60
  text ".Layer_Name" at 577,-858.49 h60
Bottom Solder:
  text ".Layer_Name" at 577,-858.49 h60
Drill Guide:
  text ".Layer_Name" at 577,-858.49 h60
M1 Board Outline:
  text ".Layer_Name" at 577,-858.49 h60
M2 Board Dimensions:
  rectangle: 125,-400 500,-275
  rectangle: 0,-275 125,-150
  rectangle: 1208,1286 1583,1411
  lines w7: 0,-275 1000,-275 ; 125,-400 125,-150 ; 250,-400 250,-150 ; 500,-400 500,-150 ; 750,-400 750,-150 ; 0,-400 0,-150 1000,-150 1000,-400 0,-400
  text ".Layer_Name" at 577,-858.49 h60
M3 3D STEP Top:
  text ".Layer_Name" at 577,-858.49 h60
M4 3D STEP Bottom:
  text ".Layer_Name" at 577,-858.49 h60
M5 Assembly Top:
  lines w10: -292,-930.17 6308,-930.17 ; -292,-726.83 6310,-726.83 ; -292,-523.5 -292,-1133.5 3713,-1133.5 6310,-1133.5 6310,-523.5 -291.5,-523.5 -291.5,-1133.5 1284,-1133.5 ; 791,552.5 791,1162.5 ; 791.5,552.5 791.5,1162.5 ; 2173,-1133.5 2173,-523.5 ; 3440,-726.83 3440,-523.5 ; 4280,-726.83 4280,-523.5 ; 4902,-1140 4902,-937.17
  text "PLOT NAME =" at 854.5,621.66 h60
  text "COMPONENTS MARKED 'DNP' SHOULD NOT BE POPULATED." at 1153.5,-318.5 h60
  text "ASSEMBLY VARIANT:" at 1153,-434 h60
  text ".VariantName" at 2189,-434 h60
  text "PCB VIEWED FROM TOP SIDE" at -228.5,-655.67 h60
  text "BOARD #:" at 2248,-655.67 h60
  text ".PRJ_Number" at 2793.5,-655.67 h60
  text "REV:" at 3638,-655.67 h60
  text ".PCB_Rev" at 3929.5,-655.67 h60
  text "SVN REV:" at 4476,-655.67 h60
  text ".VersionControl_RevNumber" at 4982,-655.67 h60
  text "TID #:" at 2248,-859 h60
  text ".TID" at 2793.5,-859 h60
  text "PLOT NAME =" at -228.5,-1064.34 h60
  text ".plot_File_Name" at 577,-1064.34 h60
  text "GENERATED    :" at 2250,-1064.34 h60
  text ".Print_Date" at 3119.5,-1064.34 h60
  text ".Print_Time" at 3848.5,-1064.34 h60
  text "TEXAS INSTRUMENTS" at 5113,-1064.34 h60
M6 Assembly Bottom:
  lines w10: -292.5,-727.33 6309.5,-727.33 ; -290.5,-930.67 6309.5,-930.67 ; 790.5,552 790.5,1162 ; 1115.5,-1140.5 1115.5,-937.67 ; 1737.5,-727.33 1737.5,-524 ; 2577.5,-727.33 2577.5,-524 ; 3844.5,-1134 3844.5,-524 ; 4733.5,-1134 6309,-1134 6309,-524 -292.5,-524 -292.5,-1134 2304.5,-1134 6309.5,-1134 6309.5,-524
  text "COMPONENTS MARKED 'DNP' SHOULD NOT BE POPULATED." at 6102,-318 h60
  text ".VariantName" at 5058,-434 h60
  text "ASSEMBLY VARIANT:" at 6097,-434 h60
  text ".VersionControl_RevNumber" at 1035.5,-656.17 h60
  text "SVN REV:" at 1541.5,-656.17 h60
  text ".PCB_Rev" at 2088,-656.17 h60
  text "REV:" at 2379.5,-656.17 h60
  text ".PRJ_Number" at 3224,-656.17 h60
  text "BOARD #:" at 3769.5,-656.17 h60
  text "PCB VIEWED FROM BOTTOM SIDE" at 6246,-656.17 h60
  text ".TID" at 3224,-859.5 h60
  text "TID #:" at 3769.5,-859.5 h60
  text "TEXAS INSTRUMENTS" at 904.5,-1064.84 h60
  text ".Print_Time" at 2169,-1064.84 h60
  text ".Print_Date" at 2898,-1064.84 h60
  text "GENERATED    :" at 3767.5,-1064.84 h60
  text ".plot_File_Name" at 5440.5,-1064.84 h60
  text "PLOT NAME =" at 6246,-1064.84 h60
M9 Title Sheet:
  drawing of 57 lines, arcs and shapes, not listed
  text "1" at 739.84,8036.5 h70
  text "2" at 3235.5,8036.5 h70
  text "3" at 5724.84,8036.5 h70
  text "4" at 8231.51,8036.5 h70
  text "5" at 10730.5,8036.5 h70
  text "6" at 13235.5,8036.5 h70
  text "A" at -416.5,6893.5 h70
  text "A" at 14383.5,6893.5 h70
  text "B" at -416.5,4513.5 h70
  text "B" at 14383.5,4513.5 h70
  text "C" at -416.5,2138.5 h70
  text "C" at 14383.5,2138.5 h70
  text "PROJECT TITLE:" at 11343.5,277.5 h45
  text "XLBOOST-SHIFTLED" at 11518,154 h80
  text "DESIGNED FOR:" at 11343.5,-23.5 h45
  text "D" at -416.5,-231.5 h70
  text "D" at 14383.5,-231.5 h70
  text "FILE NAME:" at 11343.5,-323.5 h45
  text "7segLEDmatA.PrjPcb" at 11393.5,-443.5 h70
  text "Texas Instruments (TI) and/or its licensors do not warrant the accuracy or completeness of this specification" at 6374,-605.34 h45
  text "ENGINEER:" at 11343.5,-613.5 h45
  text "LAYOUT BY:" at 12848.5,-613.5 h45
  text "or any information contained therein. TI and/or its licensors do not warrant that this design will meet" at 6329.01,-718 h45
  text "Daniel Hartung" at 11393.5,-768.49 h70
  text "Daniel Hartung" at 12899,-768.49 h70
  text "the specifications, will be suitable for your application or fit for any particular purpose, or will operate in" at 6329.01,-830.67 h45
  text ".Layer_Name" at 577,-858.49 h60
  text "ALTIUM DESIGNER VERSION:" at 12848.5,-923.5 h45
  text "an implementation. TI and/or its licensors do not warrant that the design is production worthy. You should" at 6329.01,-943.33 h45
  text "completely validate and test your design implementation to confirm the system functionality for your application." at 6374,-1056 h45
  text ".print_Scale" at 11393.5,-1056.83 h70
  text ".Application_BuildNumber" at 12899,-1056.83 h70
  text "1" at 739.84,-1263.5 h70
  text "2" at 3235.5,-1263.5 h70
  text "3" at 5724.84,-1263.5 h70
  text "4" at 8231.51,-1263.5 h70
  text "5" at 10730.5,-1263.5 h70
  text "6" at 13235.5,-1263.5 h70
M10 Fab Notes:
  drawing of 170 lines, arcs and shapes, not listed
  text "DESIGN INFORMATION" at 12378.02,6201 h60
  text "MIN. TRACK WIDTH:" at 11733.46,6021 h60
  text "2" at 12829.7,6021 h60
  text "MIL" at 12984.46,6021 h60
  text "MIN. CLEARANCE:" at 11733.46,5889 h60
  text "0.2" at 12769.7,5889 h60
  text "mm" at 12984.46,5889 h60
  text "MIN. VIA PAD SIZE:" at 11733.46,5757 h60
  text "11" at 12799.71,5757 h60
  text "MIL" at 12984.46,5757 h60
  text "0.05mm (2MIL)" at 12428.46,5615.29 h60
  text "MINIMUM ANNULAR RING" at 11404.23,5611 h60
  text "EXTERNAL" at 13136.46,5611 h60
  text "PER" at 11604.23,5493 h60
  text "IPC-D-275 CLASS 2 LEVEL C" at 11824.23,5493 h60
  text "MIL, HOLES" at 13312.46,5380.71 h60
  text "+/-" at 12920,5380 h60
  text "+/-" at 13774,5380 h60
  text "REGISTRATION TOLERANCES:" at 11404.23,5375 h60
  text "METAL" at 12604,5375 h60
  text "5" at 13180.2,5375 h60
  text "3" at 14013.2,5375 h60
  text "MIL" at 14129.46,5375 h60
  text "+/-" at 13774,5262 h60
  text "HOLE SIZE TOLERANCE (UNLESS OTHERWISE SPECIFIED):" at 11404.23,5257 h60
  text "3" at 14013.2,5257 h60
  text "MIL" at 14129.46,5257 h60
  text "MATERIAL:" at 11329.46,5047.54 h60
  text "FR-4 High Tg" at 12315.9,4907.21 h60
  text "FR-408" at 11750.46,4898.64 h60
  text "OTHER" at 13238.46,4898.64 h60
  text "X" at 12161,4895 h60
  text "62 MIL (1.6mm) +/-10%" at 12070.56,4735.92 h60
  text "THICKNESS:" at 11404.23,4731.64 h60
  text "X" at 11942.4,4731.64 h60
  text "OTHER" at 13355.46,4731.64 h60
  text "TOLERANCE:" at 11404.23,4573.64 h60
  text "X" at 12243.53,4573.64 h60
  text "ANSI IPC-6012 TYPE 3 CLASS 2" at 12430.48,4573.64 h60
  text "OTHER +/-" at 12430.46,4417.64 h60
  text "BOW & TWIST:" at 11404.23,4260.64 h60
  text "X" at 12243.53,4260.64 h60
  text "ANSI IPC-6012 TYPE 3 CLASS 2" at 12430.48,4260.64 h60
  text "OTHER +/-" at 12430.46,4102.13 h60
  text "DRILLING:" at 11329.46,3963.64 h60
  text "REFERENCE:" at 11404.23,3846.64 h60
  text "X" at 12052.46,3846.64 h60
  text "AS SHOWN" at 12239.46,3846.64 h60
  text "X" at 12953.46,3846.64 h60
  text "NC_DRILL FILES" at 13090.46,3846.64 h60
  text "PTH COPPER THICKNESS:" at 11404.23,3688.64 h60
  text "X" at 12534.46,3688.64 h60
  text "20-30 um" at 12671.46,3688.64 h60
  text "OTHER" at 13388.46,3688.64 h60
  text "BOARD FINISH:" at 11329.46,3529.64 h60
  text "SILKSCREEN:" at 11484.68,3411.64 h60
  text "X" at 12433.46,3411.64 h60
  text "TOP" at 12559.46,3411.64 h60
  text "X" at 12943.46,3411.64 h60
  text "BOTTOM" at 13070.46,3411.64 h60
  text "SILKSCREEN COLOR:" at 11484.68,3244.64 h60
  text "X" at 12432.42,3244.64 h60
  text "WHITE" at 12559.46,3244.64 h60
  text "OTHER" at 13070.46,3244.64 h60
  text "RED" at 13689.46,3094.44 h60
  text "GREEN" at 12690.46,3085.44 h60
  text "OTHER" at 13308.46,3085.44 h60
  text "X" at 13148,3081 h60
  text "SOLDER RESIST COLOR:" at 11484.68,3074.64 h60
  text "X" at 12563.42,2915.44 h60
  text "MATTE" at 12690.46,2915.44 h60
  text "SEMI-GLOSS" at 13308,2914.8 h60
  text "IMMERSION GOLD (ENIG)" at 12390.46,2726.92 h60
  text "ENEPIG" at 13728,2723.64 h60
  text "SURFACE FINISH:" at 11329.46,2722.64 h60
  text "X" at 12203.51,2722.64 h60
  text "IMM. TIN/SILVER OR EQUIV" at 11659,2565.64 h60
  text "OTHER" at 13090.46,2565.64 h60
  text "ARRAY/PANEL:" at 11329.46,2386.64 h60
  text "CUT AND TRIM PER M1 BOARD OUTLINE" at 12390.46,2382.35 h60
  text "N.C. ROUTE" at 12390.46,2230.64 h60
  text "X" at 13069.46,2230.64 h60
  text "V. SCORE" at 13256.46,2230.64 h60
  text "CERTIFICATION:" at 11329.46,2093.64 h60
  text "MATERIALS AND WORKMANSHIP FOR ALL PCBS" at 12054.46,2093.64 h60
  text "TO MEET OR EXCEED THE REQUIREMENTS OF:" at 12054.46,1995.64 h60
  text "X" at 11680.96,1859.13 h60
  text "ANSI IPC-A-600F CLASS ->" at 11819.96,1859.13 h60
  text "X" at 13459.02,1859.13 h60
  text "2" at 13577.96,1859.14 h60
  text "1" at 13262.96,1857.64 h60
  text "3" at 13931.96,1857.64 h60
  text "X" at 12495.02,1699.64 h60
  text "RoHS" at 12631.96,1699.64 h60
  text "OTHER" at 13276.36,1699.64 h60
  text "PER ORDER" at 13673.42,1699.64 h60
  text "ALL BOARDS MUST MEET OR EXCEED UL94-V0 REQUIREMENTS." at 11357,1534 h60
  text "PCB MUST BEAR THE UL94V-0 UL REGISTERED MATERIAL ID NUMBER" at 11357,1414 h60
  text "ADDITIONAL REQUIREMENTS:" at 11329.46,1240.64 h60
  text "MICROSECTION:" at 11404.23,1125.64 h60
  text "YES" at 12309.96,1125.64 h60
  text "REQUIRED" at 13171.46,969.49 h60
  text "BARE BOARD ELEC. TEST:" at 11404.23,966.64 h60
  text "NONE" at 12709.96,966.64 h60
  text "X" at 13044.46,966.64 h60
  text "PER ORDER" at 13763.46,966.64 h60
  text ".Layer_Name" at 577,-858.49 h60
M11 Gerber Information:
  lines w10: -292,-930.17 6308,-930.17 ; -292,-726.83 6310,-726.83 ; -292,-523.5 -292,-1133.5 3713,-1133.5 6310,-1133.5 6310,-523.5 -291.5,-523.5 -291.5,-1133.5 1284,-1133.5 ; 2173,-1133.5 2173,-523.5 ; 3440,-726.83 3440,-523.5 ; 4280,-726.83 4280,-523.5 ; 4902,-1140 4902,-937.17
  text "ALL ARTWORK VIEWED FROM TOP SIDE" at -228.5,-655.67 h60
  text "BOARD #:" at 2248,-655.67 h60
  text ".PRJ_Number" at 2793.5,-655.67 h60
  text "REV:" at 3638,-655.67 h60
  text ".PCB_Rev" at 3929.5,-655.67 h60
  text "SVN REV:" at 4476,-655.67 h60
  text ".VersionControl_RevNumber" at 4982,-655.67 h60
  text "LAYER NAME =" at -228.5,-858.49 h60
  text "TID #:" at 2248,-859 h60
  text ".TID" at 2793.5,-859 h60
  text "PLOT NAME =" at -228.5,-1064.34 h60
  text ".plot_File_Name" at 577,-1064.34 h60
  text "GENERATED    :" at 2250,-1064.34 h60
  text ".Print_Date" at 3119.5,-1064.34 h60
  text ".Print_Time" at 3848.5,-1064.34 h60
  text "TEXAS INSTRUMENTS" at 5113,-1064.34 h60
M12 Stackup:
  drawing of 191 lines, arcs and shapes, not listed
  text "Layer" at 9790.34,7830 h60
  text "Name" at 10200.26,7830 h60
  text "Material" at 11130,7830 h60
  text "Thickness" at 11989.77,7830 h60
  text "Constant" at 12639.6,7830 h60
  text "Board Layer Stack" at 13209.46,7830 h60
  text "1" at 9790.34,7710 h60
  text "Top Overlay" at 10200.26,7710 h60
  text "2" at 9790.34,7590 h60
  text "Top Solder" at 10200.26,7590 h60
  text "Solder Resist" at 11130,7590 h60
  text "0.40mil" at 11989.77,7590 h60
  text "3.5" at 12639.6,7590 h60
  text "3" at 9790.34,7470 h60
  text "Top Layer" at 10200.26,7470 h60
  text "Copper" at 11130,7470 h60
  text "1.40mil" at 11989.77,7470 h60
  text "4" at 9790.34,7350 h60
  text "Dielectric1" at 10200.26,7350 h60
  text "FR-4" at 11130,7350 h60
  text "59.20mil" at 11989.77,7350 h60
  text "4.8" at 12639.6,7350 h60
  text "5" at 9790.34,7230 h60
  text "Bottom Layer" at 10200.26,7230 h60
  text "Copper" at 11130,7230 h60
  text "1.40mil" at 11989.77,7230 h60
  text "6" at 9790.34,7110 h60
  text "Bottom Solder" at 10200.26,7110 h60
  text "Solder Resist" at 11130,7110 h60
  text "0.40mil" at 11989.77,7110 h60
  text "3.5" at 12639.6,7110 h60
  text "7" at 9790.34,6990 h60
  text "Bottom Overlay" at 10200.26,6990 h60
  text ".Layer_Name" at 577,-858.49 h60
M13 Component Bodies Top:
  text ".Layer_Name" at 577,-858.49 h60
M14 Component Bodies Bottom:
  text ".Layer_Name" at 577,-858.49 h60
M15 Courtyards Top:
  text ".Layer_Name" at 577,-858.49 h60
M16 Courtyards Bottom:
  text ".Layer_Name" at 577,-858.49 h60
Drill Drawing:
  circle w10: c5348.8,3104.14 r22.1
  lines w10: 5326.69,2684.23 5370.9,2684.23 5370.9,2728.44 5326.69,2728.44 5326.69,2684.23 ; 5326.69,2805.78 5348.8,2783.69 5370.9,2805.78 5348.8,2827.89 5326.69,2805.78 ; 5326.69,2894.19 5337.74,2894.19 5337.74,2883.14 5359.85,2883.14 5359.85,2894.19 5370.9,2894.19 5370.9,2916.28 5359.85,2916.28 5359.85,2927.34 5337.74,2927.34 5337.74,2916.28 5326.69,2916.28 5326.69,2894.19 ; 5326.69,2982.59 5348.8,2993.64 5370.9,2982.59 5359.85,3004.69 5370.9,3026.78 5348.8,3015.73 5326.69,3026.78 5337.74,3004.69 5326.69,2982.59 ; 5326.69,3192.53 5337.74,3192.53 5348.8,3181.48 5359.85,3192.53 5370.9,3192.53 5359.85,3203.59 5370.9,3214.64 5359.85,3214.64 5348.8,3225.69 5337.74,3214.64 5326.69,3214.64 5337.74,3203.59 5326.69,3192.53 ; 5326.69,3280.94 5326.69,3291.98 5337.74,3303.03 5326.69,3314.09 5326.69,3325.14 5337.74,3325.14 5348.8,3314.09 5359.85,3325.14 5370.9,3325.14 5370.9,3314.09 5359.85,3303.03 5370.9,3291.98 5370.9,3280.94 5359.85,3280.94 5348.8,3291.98 5337.74,3280.94 5326.69,3280.94
  lines w12: 5286,2654.4 8398.72,2654.4 ; 5286,3350.55 8398.72,3350.55 ; 5601.66,2554.95 5601.66,3450 ; 5918.77,2554.95 5918.77,3450 ; 6540.77,2554.95 6540.77,3450 ; 6785.12,2554.95 6785.12,3450 ; 7145.53,2554.95 7145.53,3450 ; 7854.37,2554.95 7854.37,3450 ; 5286,2554.95 8398.72,2554.95 8398.72,3450 5286,3450 5286,2554.95
  text "Symbol" at 5345.67,3380.39 h72
  text "Quantity" at 5631.5,3380.39 h72
  text "Finished Hole Size" at 5948.6,3380.39 h72
  text "Plated" at 6570.6,3380.39 h72
  text "Hole Type" at 6814.95,3380.39 h72
  text "Drill Layer Pair" at 7175.36,3380.39 h72
  text "Hole Tolerance" at 7884.21,3380.39 h72
  text "172" at 5631.5,3280.94 h60
  text "5.00mil (0.127mm)" at 5948.6,3280.94 h60
  text "PTH" at 6570.6,3280.94 h60
  text "Round" at 6814.95,3280.94 h60
  text "Top Layer - Bottom Layer" at 7175.36,3280.94 h60
  text "27" at 5631.5,3181.48 h60
  text "7.87mil (0.200mm)" at 5948.6,3181.48 h60
  text "PTH" at 6570.6,3181.48 h60
  text "Round" at 6814.95,3181.48 h60
  text "Top Layer - Bottom Layer" at 7175.36,3181.48 h60
  text "36" at 5631.5,3082.03 h60
  text "8.00mil (0.203mm)" at 5948.6,3082.03 h60
  text "PTH" at 6570.6,3082.03 h60
  text "Round" at 6814.95,3082.03 h60
  text "Top Layer - Bottom Layer" at 7175.36,3082.03 h60
  text "6" at 5631.5,2982.59 h60
  text "10.00mil (0.254mm)" at 5948.6,2982.59 h60
  text "PTH" at 6570.6,2982.59 h60
  text "Round" at 6814.95,2982.59 h60
  text "Top Layer - Bottom Layer" at 7175.36,2982.59 h60
  text "40" at 5631.5,2883.14 h60
  text "31.50mil (0.800mm)" at 5948.6,2883.14 h60
  text "PTH" at 6570.6,2883.14 h60
  text "Round" at 6814.95,2883.14 h60
  text "Top Layer - Bottom Layer" at 7175.36,2883.14 h60
  text "10" at 5631.5,2783.69 h60
  text "40.00mil (1.016mm)" at 5948.6,2783.69 h60
  text "PTH" at 6570.6,2783.69 h60
  text "Round" at 6814.95,2783.69 h60
  text "Top Layer - Bottom Layer" at 7175.36,2783.69 h60
  text "43" at 5631.5,2684.23 h60
  text "40.16mil (1.020mm)" at 5948.6,2684.23 h60
  text "PTH" at 6570.6,2684.23 h60
  text "Round" at 6814.95,2684.23 h60
  text "Top Layer - Bottom Layer" at 7175.36,2684.23 h60
  text "334 Total" at 5631.5,2584.78 h60
  text ".Layer_Name" at 577,-858.49 h60
Mechanical 17:
  text ".Layer_Name" at 577,-858.49 h60
Mechanical 18:
  text ".Layer_Name" at 577,-858.49 h60
Mechanical 19:
  text ".Layer_Name" at 577,-858.49 h60

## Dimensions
0,-400 to 1000,-400 on M2 Board Dimensions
